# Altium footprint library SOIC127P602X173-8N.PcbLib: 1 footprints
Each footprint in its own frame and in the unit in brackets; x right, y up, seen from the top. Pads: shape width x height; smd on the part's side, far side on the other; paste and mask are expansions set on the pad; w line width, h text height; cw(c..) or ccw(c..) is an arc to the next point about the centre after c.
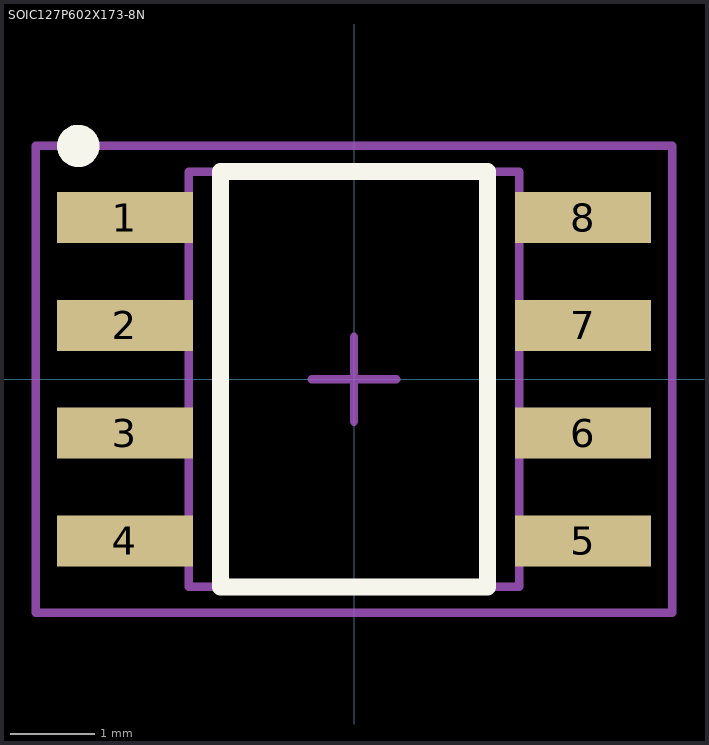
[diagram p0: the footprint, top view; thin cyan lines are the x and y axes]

## SOIC127P602X173-8N [mm] "SOIC,1.27mm pitch;8 pin,3.899mm W X 4.889mm L X 1.727mm H body"
height 1.727
pads (8):
  rect 1.6x0.6 smd paste+0 mask+0: 1(-2.7,1.905) 2(-2.7,0.635) 3(-2.7,-0.635) 4(-2.7,-1.905) 5(2.7,-1.905) 6(2.7,-0.635) 7(2.7,0.635) 8(2.7,1.905)
Top Overlay:
  circle w0.25: c-3.25,2.75 r0.125
  lines w0.2: -1.575,-2.45 -1.575,2.45 1.575,2.45 1.575,-2.45 -1.575,-2.45
Mechanical 3:
  text ".DESIGNATOR" at 0,0 h1.2
Mechanical 13:
  lines w0.1: -1.949,-2.444 1.949,-2.444 1.949,2.444 -1.949,2.444 -1.949,-2.444
Mechanical 15:
  lines w0.1: -0.5,0 0.5,0 ; 0,-0.5 0,0.5 ; -3.75,-2.75 -3.75,2.75 3.75,2.75 3.75,-2.75 -3.75,-2.75
3D body: height 0.85, standoff 0.6, extent 1.949,1.7 2.234,2.12
3D body: height 0.72, standoff 0.13, extent 2.109,1.7 2.359,2.12
3D body: height 0.25, standoff 0, extent 2.234,1.7 3.009,2.12
3D body: height 0.85, standoff 0.6, extent 2.109,1.7 2.358,2.12
3D body: height 0.25, standoff 0, extent 2.109,1.7 2.358,2.12
3D body: height 0.85, standoff 0.6, extent 1.949,0.43 2.234,0.85
3D body: height 0.72, standoff 0.13, extent 2.109,0.43 2.359,0.85
3D body: height 0.25, standoff 0, extent 2.234,0.43 3.009,0.85
3D body: height 0.85, standoff 0.6, extent 2.109,0.43 2.358,0.85
3D body: height 0.25, standoff 0, extent 2.109,0.43 2.358,0.85
3D body: height 0.85, standoff 0.6, extent 1.949,-0.84 2.234,-0.42
3D body: height 0.72, standoff 0.13, extent 2.109,-0.84 2.359,-0.42
3D body: height 0.25, standoff 0, extent 2.234,-0.84 3.009,-0.42
3D body: height 0.85, standoff 0.6, extent 2.109,-0.84 2.358,-0.42
3D body: height 0.25, standoff 0, extent 2.109,-0.84 2.358,-0.42
3D body: height 0.85, standoff 0.6, extent 1.949,-2.11 2.234,-1.69
3D body: height 0.72, standoff 0.13, extent 2.109,-2.11 2.359,-1.69
3D body: height 0.25, standoff 0, extent 2.234,-2.11 3.009,-1.69
3D body: height 0.85, standoff 0.6, extent 2.109,-2.11 2.358,-1.69
3D body: height 0.25, standoff 0, extent 2.109,-2.11 2.358,-1.69
3D body: height 0.85, standoff 0.6, extent -2.234,-2.12 -1.949,-1.7
3D body: height 0.72, standoff 0.13, extent -2.359,-2.12 -2.109,-1.7
3D body: height 0.25, standoff 0, extent -3.009,-2.12 -2.234,-1.7
3D body: height 0.85, standoff 0.6, extent -2.358,-2.12 -2.109,-1.7
3D body: height 0.25, standoff 0, extent -2.358,-2.12 -2.109,-1.7
3D body: height 0.85, standoff 0.6, extent -2.234,-0.85 -1.949,-0.43
3D body: height 0.72, standoff 0.13, extent -2.359,-0.85 -2.109,-0.43
3D body: height 0.25, standoff 0, extent -3.009,-0.85 -2.234,-0.43
3D body: height 0.85, standoff 0.6, extent -2.358,-0.85 -2.109,-0.43
3D body: height 0.25, standoff 0, extent -2.358,-0.85 -2.109,-0.43
3D body: height 0.85, standoff 0.6, extent -2.234,0.42 -1.949,0.84
3D body: height 0.72, standoff 0.13, extent -2.359,0.42 -2.109,0.84
3D body: height 0.25, standoff 0, extent -3.009,0.42 -2.234,0.84
3D body: height 0.85, standoff 0.6, extent -2.358,0.42 -2.109,0.84
3D body: height 0.25, standoff 0, extent -2.358,0.42 -2.109,0.84
3D body: height 1.73, standoff 0.1, extent -1.949,-2.444 1.949,2.444
3D body: height 1.73, standoff 1.73, extent -1.745,1.791 -1.496,2.041
3D body: height 0.25, standoff 0, extent -2.358,1.69 -2.109,2.11
3D body: height 0.85, standoff 0.6, extent -2.358,1.69 -2.109,2.11
3D body: height 0.25, standoff 0, extent -3.009,1.69 -2.234,2.11
3D body: height 0.72, standoff 0.13, extent -2.359,1.69 -2.109,2.11
3D body: height 0.85, standoff 0.6, extent -2.234,1.69 -1.949,2.11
